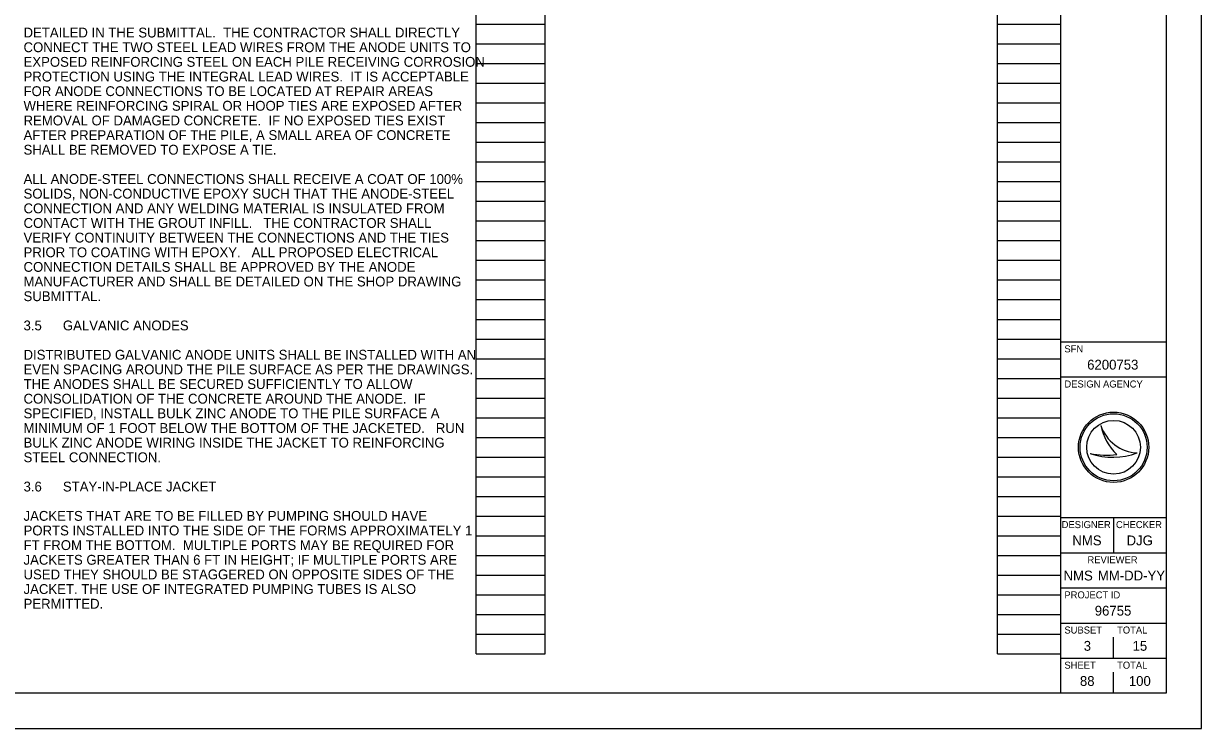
# Model space of a CAD drawing. Extents: x -0.5 to 34, y 0 to 22.
# Drawn here: x 17.24 to 34, y 0 to 10.03 of the extents above; entities that cross this region are included whole.
import ezdxf

# ---------------------------------------------------------------- set-up
doc = ezdxf.new("R2010")
doc.units = 0
for name, color, linetype in [('SH_Border', 7, 'Continuous'), ('SH_Cut_Line', 7, 'Continuous'), ('SH_Data', 7, 'Continuous'), ('SH_Text', 7, 'Continuous')]:
    doc.layers.add(name, color=color, linetype=linetype)

msp = doc.modelspace()

# ---------------------------------------------------------------- linework, layer by layer
at = {"layer": 'SH_Border'}
for p, q in [((32, 0.5), (32, 21.5)), ((32, 5.5), (33.5, 5.5)), ((32, 5), (33.5, 5)), ((32, 3), (33.5, 3)), ((32.75, 3), (32.75, 2.5)), ((32, 2.5), (33.5, 2.5)), ((32, 2), (33.5, 2)), ((32, 1.5), (33.5, 1.5)), ((32, 1), (33.5, 1))]:
    msp.add_line(p, q, dxfattribs=at)
msp.add_lwpolyline([(1.5, 21.5), (33.5, 21.5), (33.5, 0.5), (1.5, 0.5)], close=True, dxfattribs=at)
at = {"layer": 'SH_Cut_Line'}
msp.add_lwpolyline([(0, 0), (34, 0), (34, 22), (0, 22)], close=True, dxfattribs=at)
at = {"layer": 'SH_Data'}
for p, q in [((23.68, 1.06), (23.68, 21.22)), ((24.66, 1.06), (24.66, 21.22)), ((31.1, 1.06), (31.1, 21.22)), ((32, 1.06), (32, 21.22)), ((23.68, 10.02), (24.66, 10.02)), ((31.1, 10.02), (32, 10.02)), ((23.68, 9.74), (24.66, 9.74)), ((31.1, 9.74), (32, 9.74)), ((23.68, 9.46), (24.66, 9.46)), ((31.1, 9.46), (32, 9.46)), ((23.68, 9.18), (24.66, 9.18)), ((31.1, 9.18), (32, 9.18)), ((23.68, 8.9), (24.66, 8.9)), ((31.1, 8.9), (32, 8.9)), ((23.68, 8.62), (24.66, 8.62)), ((31.1, 8.62), (32, 8.62)), ((23.68, 8.34), (24.66, 8.34)), ((31.1, 8.34), (32, 8.34)), ((23.68, 8.06), (24.66, 8.06)), ((31.1, 8.06), (32, 8.06)), ((23.68, 7.78), (24.66, 7.78)), ((31.1, 7.78), (32, 7.78)), ((23.68, 7.5), (24.66, 7.5)), ((31.1, 7.5), (32, 7.5)), ((23.68, 7.22), (24.66, 7.22)), ((31.1, 7.22), (32, 7.22)), ((23.68, 6.94), (24.66, 6.94)), ((31.1, 6.94), (32, 6.94)), ((23.68, 6.66), (24.66, 6.66)), ((31.1, 6.66), (32, 6.66)), ((23.68, 6.38), (24.66, 6.38)), ((31.1, 6.38), (32, 6.38)), ((23.68, 6.1), (24.66, 6.1)), ((31.1, 6.1), (32, 6.1)), ((23.68, 5.82), (24.66, 5.82)), ((31.1, 5.82), (32, 5.82)), ((23.68, 5.54), (24.66, 5.54)), ((31.1, 5.54), (32, 5.54)), ((23.68, 5.26), (24.66, 5.26)), ((31.1, 5.26), (32, 5.26)), ((23.68, 4.98), (24.66, 4.98)), ((31.1, 4.98), (32, 4.98)), ((23.68, 4.7), (24.66, 4.7)), ((31.1, 4.7), (32, 4.7)), ((23.68, 4.42), (24.66, 4.42)), ((31.1, 4.42), (32, 4.42)), ((32.567, 4.31), (32.567, 4.31)), ((23.68, 4.14), (24.66, 4.14)), ((31.1, 4.14), (32, 4.14)), ((23.68, 3.86), (24.66, 3.86)), ((31.1, 3.86), (32, 3.86)), ((32.417, 3.91), (32.417, 3.91)), ((32.75, 4), (32.75, 4)), ((33.087, 3.919), (33.087, 3.919)), ((23.68, 3.58), (24.66, 3.58)), ((31.1, 3.58), (32, 3.58)), ((23.68, 3.3), (24.66, 3.3)), ((31.1, 3.3), (32, 3.3)), ((23.68, 3.02), (24.66, 3.02)), ((31.1, 3.02), (32, 3.02)), ((23.68, 2.74), (24.66, 2.74)), ((31.1, 2.74), (32, 2.74)), ((23.68, 2.46), (24.66, 2.46)), ((31.1, 2.46), (32, 2.46)), ((23.68, 2.18), (24.66, 2.18)), ((31.1, 2.18), (32, 2.18)), ((23.68, 1.9), (24.66, 1.9)), ((31.1, 1.9), (32, 1.9)), ((23.68, 1.62), (24.66, 1.62)), ((31.1, 1.62), (32, 1.62)), ((23.68, 1.34), (24.66, 1.34)), ((31.1, 1.34), (32, 1.34)), ((32.75, 1), (32.75, 1.3)), ((23.68, 1.06), (24.66, 1.06)), ((31.1, 1.06), (32, 1.06)), ((32.375, 0.675), (32.375, 0.675)), ((32.75, 0.5), (32.75, 0.8))]:
    msp.add_line(p, q, dxfattribs=at)
for radius in [0.5, 0.477, 0.477, 0.382]:
    msp.add_circle((32.75, 4), radius, dxfattribs=at)
for centre, radius, start, end in [((33.116, 4.498), 0.58, 198.9257, 198.9319), ((33.347, 4.47), 0.796, 191.6379, 191.6421), ((33.116, 4.498), 0.58, 198.9319, 267.1657), ((33.347, 4.47), 0.796, 191.6421, 226.0947), ((32.739, 4.87), 1.013, 251.4576, 290.0832), ((32.648, 5.154), 1.266, 259.4964, 259.4995), ((32.739, 4.87), 1.013, 251.4527, 251.4576), ((32.648, 5.154), 1.266, 259.4995, 276.6672)]:
    msp.add_arc(centre, radius, start, end, dxfattribs=at)

# ---------------------------------------------------------------- texts
for s, height, p in [('SFN', 0.1, (32.05, 5.35)), ('6200753', 0.14, (32.374, 5.105)), ('DESIGN AGENCY', 0.1, (32.05, 4.85)), ('DESIGNER', 0.1, (32.011, 2.85)), ('CHECKER', 0.1, (32.784, 2.85)), ('NMS', 0.14, (32.163, 2.605)), ('DJG', 0.14, (32.935, 2.605)), ('REVIEWER', 0.1, (32.378, 2.35)), ('NMS', 0.14, (32.038, 2.105)), ('MM-DD-YY', 0.14, (32.526, 2.105)), ('PROJECT ID', 0.1, (32.05, 1.85)), ('96755', 0.14, (32.482, 1.605)), ('SUBSET', 0.1, (32.05, 1.35)), ('TOTAL', 0.1, (32.8, 1.35)), ('3', 0.14, (32.325, 1.105)), ('15', 0.14, (33.02, 1.105)), ('SHEET', 0.1, (32.05, 0.85)), ('TOTAL', 0.1, (32.8, 0.85)), ('88', 0.14, (32.271, 0.605)), ('100', 0.14, (32.967, 0.605))]:
    msp.add_text(s, height=height, dxfattribs=at).set_placement(p)
at = {"layer": 'SH_Text'}
for s, p in [('DETAILED IN THE SUBMITTAL.  THE CONTRACTOR SHALL DIRECTLY ', (17.24, 9.83)), ('CONNECT THE TWO STEEL LEAD WIRES FROM THE ANODE UNITS TO ', (17.24, 9.621)), ('EXPOSED REINFORCING STEEL ON EACH PILE RECEIVING CORROSION ', (17.24, 9.413)), ('PROTECTION USING THE INTEGRAL LEAD WIRES.  IT IS ACCEPTABLE ', (17.24, 9.204)), ('FOR ANODE CONNECTIONS TO BE LOCATED AT REPAIR AREAS ', (17.24, 8.996)), ('WHERE REINFORCING SPIRAL OR HOOP TIES ARE EXPOSED AFTER ', (17.24, 8.788)), ('REMOVAL OF DAMAGED CONCRETE.  IF NO EXPOSED TIES EXIST ', (17.24, 8.579)), ('AFTER PREPARATION OF THE PILE, A SMALL AREA OF CONCRETE ', (17.24, 8.371)), ('SHALL BE REMOVED TO EXPOSE A TIE.  ', (17.24, 8.163)), ('ALL ANODE-STEEL CONNECTIONS SHALL RECEIVE A COAT OF 100% ', (17.24, 7.746)), ('SOLIDS, NON-CONDUCTIVE EPOXY SUCH THAT THE ANODE-STEEL ', (17.24, 7.538)), ('CONNECTION AND ANY WELDING MATERIAL IS INSULATED FROM ', (17.24, 7.329)), ('CONTACT WITH THE GROUT INFILL.   THE CONTRACTOR SHALL ', (17.24, 7.121)), ('VERIFY CONTINUITY BETWEEN THE CONNECTIONS AND THE TIES ', (17.24, 6.913)), ('PRIOR TO COATING WITH EPOXY.   ALL PROPOSED ELECTRICAL ', (17.24, 6.704)), ('CONNECTION DETAILS SHALL BE APPROVED BY THE ANODE ', (17.24, 6.496)), ('MANUFACTURER AND SHALL BE DETAILED ON THE SHOP DRAWING ', (17.24, 6.288)), ('SUBMITTAL.  ', (17.24, 6.079)), ('3.5', (17.24, 5.663)), ('GALVANIC ANODES', (17.8, 5.663)), ('DISTRIBUTED GALVANIC ANODE UNITS SHALL BE INSTALLED WITH AN ', (17.24, 5.246)), ('EVEN SPACING AROUND THE PILE SURFACE AS PER THE DRAWINGS.  ', (17.24, 5.038)), ('THE ANODES SHALL BE SECURED SUFFICIENTLY TO ALLOW ', (17.24, 4.829)), ('CONSOLIDATION OF THE CONCRETE AROUND THE ANODE.  IF ', (17.24, 4.621)), ('SPECIFIED, INSTALL BULK ZINC ANODE TO THE PILE SURFACE A ', (17.24, 4.413)), ('MINIMUM OF 1 FOOT BELOW THE BOTTOM OF THE JACKETED.   RUN ', (17.24, 4.204)), ('BULK ZINC ANODE WIRING INSIDE THE JACKET TO REINFORCING ', (17.24, 3.996)), ('STEEL CONNECTION.   ', (17.24, 3.788)), ('3.6', (17.24, 3.371)), ('STAY-IN-PLACE JACKET', (17.8, 3.371)), ('JACKETS THAT ARE TO BE FILLED BY PUMPING SHOULD HAVE ', (17.24, 2.954)), ('PORTS INSTALLED INTO THE SIDE OF THE FORMS APPROXIMATELY 1 ', (17.24, 2.746)), ('FT FROM THE BOTTOM.  MULTIPLE PORTS MAY BE REQUIRED FOR ', (17.24, 2.538)), ('JACKETS GREATER THAN 6 FT IN HEIGHT; IF MULTIPLE PORTS ARE ', (17.24, 2.329)), ('USED THEY SHOULD BE STAGGERED ON OPPOSITE SIDES OF THE ', (17.24, 2.121)), ('JACKET. THE USE OF INTEGRATED PUMPING TUBES IS ALSO ', (17.24, 1.913)), ('PERMITTED. ', (17.24, 1.704))]:
    msp.add_text(s, height=0.14, dxfattribs=at).set_placement(p)

doc.saveas('drawing.dxf')
